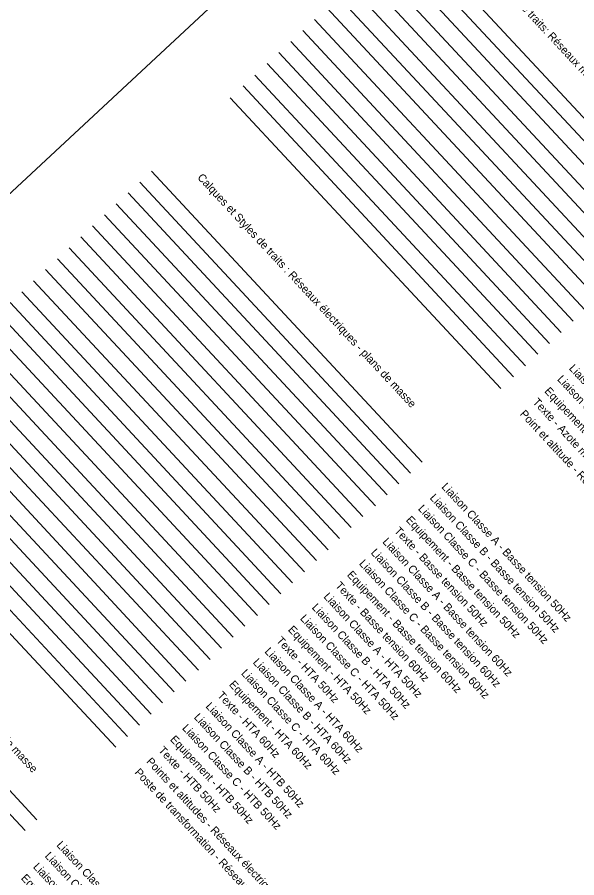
# Model space of a CAD drawing. Extents: x 704383 to 706615, y 7057567 to 7059313.
# Drawn here: x 706440.3 to 706475.2, y 7057729.7 to 7057783.5 of the extents above; entities that cross this region are included whole.
import ezdxf

# ---------------------------------------------------------------- set-up
doc = ezdxf.new("R2010")
doc.units = 0
for name, color, linetype in [('DH_CADRE -CARTOUCHE', 7, 'Continuous'), ('R_ELEC_ALT_POINT', 7, 'Continuous'), ('R_ELEC_BT_50HZ_EQUIP', 7, 'Continuous'), ('R_ELEC_BT_50HZ_LIAISON_CL_A', 7, 'Continuous'), ('R_ELEC_BT_50HZ_LIAISON_CL_B', 7, 'Continuous'), ('R_ELEC_BT_50HZ_LIAISON_CL_C', 7, 'Continuous'), ('R_ELEC_BT_50HZ_TEXTE', 7, 'Continuous'), ('R_ELEC_BT_60HZ_EQUIP', 7, 'Continuous'), ('R_ELEC_BT_60HZ_LIAISON_CL_A', 7, 'Continuous'), ('R_ELEC_BT_60HZ_LIAISON_CL_B', 7, 'Continuous'), ('R_ELEC_BT_60HZ_LIAISON_CL_C', 7, 'Continuous'), ('R_ELEC_BT_60HZ_TEXTE', 7, 'Continuous'), ('R_ELEC_HTA_50HZ_EQUIP', 7, 'Continuous'), ('R_ELEC_HTA_50HZ_LIAISON_CL_A', 7, 'Continuous'), ('R_ELEC_HTA_50HZ_LIAISON_CL_B', 7, 'Continuous'), ('R_ELEC_HTA_50HZ_LIAISON_CL_C', 7, 'Continuous'), ('R_ELEC_HTA_50HZ_TEXTE', 7, 'Continuous'), ('R_ELEC_HTA_60HZ_EQUIP', 7, 'Continuous'), ('R_ELEC_HTA_60HZ_LIAISON_CL_A', 7, 'Continuous'), ('R_ELEC_HTA_60HZ_LIAISON_CL_B', 7, 'Continuous'), ('R_ELEC_HTA_60HZ_LIAISON_CL_C', 7, 'Continuous'), ('R_ELEC_HTA_60HZ_TEXTE', 7, 'Continuous'), ('R_ELEC_HTB_50HZ_EQUIP', 7, 'Continuous'), ('R_ELEC_HTB_50HZ_LIAISON_CL_A', 7, 'Continuous'), ('R_ELEC_HTB_50HZ_LIAISON_CL_B', 7, 'Continuous'), ('R_ELEC_HTB_50HZ_LIAISON_CL_C', 7, 'Continuous'), ('R_ELEC_HTB_50HZ_TEXTE', 7, 'Continuous'), ('R_ELEC_IST_BT_50HZ_EQUIP', 7, 'Continuous'), ('R_ELEC_IST_BT_50HZ_LIAISON_CL_A', 7, 'Continuous'), ('R_ELEC_IST_BT_50HZ_LIAISON_CL_B', 7, 'Continuous'), ('R_ELEC_IST_BT_50HZ_LIAISON_CL_C', 7, 'Continuous'), ('R_ELEC_POSTE', 7, 'Continuous'), ('R_MED_ALT_POINT', 7, 'Continuous'), ('R_MED_AZOTE_CANALISATION_CL_A', 7, 'Continuous'), ('R_MED_AZOTE_CANALISATION_CL_B', 7, 'Continuous'), ('R_MED_AZOTE_CANALISATION_CL_C', 7, 'Continuous'), ('R_MED_AZOTE_EQUIP', 7, 'Continuous'), ('R_MED_AZOTE_TEXTE', 7, 'Continuous'), ('R_MED_OXYGENE_CANALISATION_CL_A', 7, 'Continuous'), ('R_MED_OXYGENE_CANALISATION_CL_B', 7, 'Continuous'), ('R_MED_OXYGENE_CANALISATION_CL_C', 7, 'Continuous'), ('R_MED_OXYGENE_EQUIP', 7, 'Continuous'), ('R_MED_OXYGENE_TEXTE', 7, 'Continuous'), ('R_MED_VIDE_CANALISATION_CL_A', 7, 'Continuous'), ('R_MED_VIDE_CANALISATION_CL_B', 7, 'Continuous'), ('R_MED_VIDE_CANALISATION_CL_C', 7, 'Continuous'), ('R_MED_VIDE_EQUIP', 7, 'Continuous'), ('R_MED_VIDE_TEXTE', 7, 'Continuous')]:
    doc.layers.add(name, color=color, linetype=linetype)

msp = doc.modelspace()

# ---------------------------------------------------------------- linework, layer by layer
at = {"layer": 'DH_CADRE -CARTOUCHE'}
msp.add_lwpolyline([(706481.837, 7057811.547), (706566.98, 7057720.028), (706402.247, 7057566.771), (706317.104, 7057658.289)], close=True, dxfattribs=at)
at = {"layer": 'R_ELEC_ALT_POINT'}
msp.add_line((706430.26, 7057756.734), (706447.172, 7057738.555), dxfattribs=at)
at = {"layer": 'R_ELEC_BT_50HZ_EQUIP'}
msp.add_line((706446.481, 7057771.824), (706463.393, 7057753.645), dxfattribs=at)
at = {"layer": 'R_ELEC_BT_50HZ_LIAISON_CL_A'}
msp.add_line((706448.677, 7057773.868), (706465.59, 7057755.689), dxfattribs=at)
at = {"layer": 'R_ELEC_BT_50HZ_LIAISON_CL_B'}
msp.add_line((706447.945, 7057773.187), (706464.857, 7057755.008), dxfattribs=at)
at = {"layer": 'R_ELEC_BT_50HZ_LIAISON_CL_C'}
msp.add_line((706447.213, 7057772.505), (706464.125, 7057754.327), dxfattribs=at)
at = {"layer": 'R_ELEC_BT_50HZ_TEXTE'}
msp.add_line((706445.748, 7057771.143), (706462.661, 7057752.964), dxfattribs=at)
at = {"layer": 'R_ELEC_BT_60HZ_EQUIP'}
msp.add_line((706442.797, 7057768.397), (706459.71, 7057750.219), dxfattribs=at)
at = {"layer": 'R_ELEC_BT_60HZ_LIAISON_CL_A'}
msp.add_line((706444.994, 7057770.441), (706461.881, 7057752.289), dxfattribs=at)
at = {"layer": 'R_ELEC_BT_60HZ_LIAISON_CL_B'}
msp.add_line((706444.261, 7057769.76), (706461.149, 7057751.608), dxfattribs=at)
at = {"layer": 'R_ELEC_BT_60HZ_LIAISON_CL_C'}
msp.add_line((706443.529, 7057769.079), (706460.417, 7057750.927), dxfattribs=at)
at = {"layer": 'R_ELEC_BT_60HZ_TEXTE'}
msp.add_line((706442.065, 7057767.716), (706458.977, 7057749.537), dxfattribs=at)
at = {"layer": 'R_ELEC_HTA_50HZ_EQUIP'}
msp.add_line((706439.114, 7057764.971), (706456.026, 7057746.792), dxfattribs=at)
at = {"layer": 'R_ELEC_HTA_50HZ_LIAISON_CL_A'}
msp.add_line((706441.31, 7057767.014), (706458.228, 7057748.829), dxfattribs=at)
at = {"layer": 'R_ELEC_HTA_50HZ_LIAISON_CL_B'}
msp.add_line((706440.578, 7057766.333), (706457.496, 7057748.148), dxfattribs=at)
at = {"layer": 'R_ELEC_HTA_50HZ_LIAISON_CL_C'}
msp.add_line((706439.846, 7057765.652), (706456.764, 7057747.467), dxfattribs=at)
at = {"layer": 'R_ELEC_HTA_50HZ_TEXTE'}
msp.add_line((706438.382, 7057764.29), (706455.294, 7057746.111), dxfattribs=at)
at = {"layer": 'R_ELEC_HTA_60HZ_EQUIP'}
msp.add_line((706435.43, 7057761.544), (706452.343, 7057743.365), dxfattribs=at)
at = {"layer": 'R_ELEC_HTA_60HZ_LIAISON_CL_A'}
msp.add_line((706437.627, 7057763.587), (706454.514, 7057745.435), dxfattribs=at)
at = {"layer": 'R_ELEC_HTA_60HZ_LIAISON_CL_B'}
msp.add_line((706436.895, 7057762.906), (706453.782, 7057744.754), dxfattribs=at)
at = {"layer": 'R_ELEC_HTA_60HZ_LIAISON_CL_C'}
msp.add_line((706436.162, 7057762.225), (706453.05, 7057744.073), dxfattribs=at)
at = {"layer": 'R_ELEC_HTA_60HZ_TEXTE'}
msp.add_line((706434.698, 7057760.863), (706451.611, 7057742.684), dxfattribs=at)
at = {"layer": 'R_ELEC_HTB_50HZ_EQUIP'}
msp.add_line((706431.747, 7057758.117), (706448.659, 7057739.938), dxfattribs=at)
at = {"layer": 'R_ELEC_HTB_50HZ_LIAISON_CL_A'}
msp.add_line((706433.946, 7057760.163), (706450.833, 7057742.011), dxfattribs=at)
at = {"layer": 'R_ELEC_HTB_50HZ_LIAISON_CL_B'}
msp.add_line((706433.214, 7057759.482), (706450.101, 7057741.33), dxfattribs=at)
at = {"layer": 'R_ELEC_HTB_50HZ_LIAISON_CL_C'}
msp.add_line((706432.482, 7057758.801), (706449.369, 7057740.649), dxfattribs=at)
at = {"layer": 'R_ELEC_HTB_50HZ_TEXTE'}
msp.add_line((706431.015, 7057757.436), (706447.927, 7057739.257), dxfattribs=at)
at = {"layer": 'R_ELEC_IST_BT_50HZ_LIAISON_CL_A'}
msp.add_line((706424.63, 7057751.496), (706441.512, 7057733.349), dxfattribs=at)
at = {"layer": 'R_ELEC_IST_BT_50HZ_LIAISON_CL_B'}
msp.add_line((706423.898, 7057750.814), (706440.78, 7057732.668), dxfattribs=at)
at = {"layer": 'R_ELEC_POSTE'}
msp.add_line((706429.528, 7057756.052), (706446.44, 7057737.874), dxfattribs=at)
at = {"layer": 'R_MED_ALT_POINT'}
msp.add_line((706470.5, 7057760.278), (706453.598, 7057778.446), dxfattribs=at)
at = {"layer": 'R_MED_AZOTE_CANALISATION_CL_A'}
msp.add_line((706457.372, 7057781.957), (706474.274, 7057763.789), dxfattribs=at)
at = {"layer": 'R_MED_AZOTE_CANALISATION_CL_B'}
msp.add_line((706456.64, 7057781.276), (706473.542, 7057763.108), dxfattribs=at)
at = {"layer": 'R_MED_AZOTE_CANALISATION_CL_C'}
msp.add_line((706455.908, 7057780.595), (706472.81, 7057762.427), dxfattribs=at)
at = {"layer": 'R_MED_AZOTE_EQUIP'}
msp.add_line((706472.033, 7057761.703), (706455.13, 7057779.871), dxfattribs=at)
at = {"layer": 'R_MED_AZOTE_TEXTE'}
msp.add_line((706471.3, 7057761.022), (706454.398, 7057779.19), dxfattribs=at)
at = {"layer": 'R_MED_OXYGENE_CANALISATION_CL_A'}
msp.add_line((706464.807, 7057788.874), (706481.709, 7057770.706), dxfattribs=at)
at = {"layer": 'R_MED_OXYGENE_CANALISATION_CL_B'}
msp.add_line((706464.098, 7057788.214), (706481, 7057770.046), dxfattribs=at)
at = {"layer": 'R_MED_OXYGENE_CANALISATION_CL_C'}
msp.add_line((706463.365, 7057787.533), (706480.268, 7057769.365), dxfattribs=at)
at = {"layer": 'R_MED_OXYGENE_EQUIP'}
msp.add_line((706479.49, 7057768.641), (706462.588, 7057786.81), dxfattribs=at)
at = {"layer": 'R_MED_OXYGENE_TEXTE'}
msp.add_line((706478.758, 7057767.96), (706461.856, 7057786.128), dxfattribs=at)
at = {"layer": 'R_MED_VIDE_CANALISATION_CL_A'}
msp.add_line((706461.101, 7057785.426), (706477.993, 7057767.269), dxfattribs=at)
at = {"layer": 'R_MED_VIDE_CANALISATION_CL_B'}
msp.add_line((706460.369, 7057784.745), (706477.261, 7057766.588), dxfattribs=at)
at = {"layer": 'R_MED_VIDE_CANALISATION_CL_C'}
msp.add_line((706459.637, 7057784.064), (706476.529, 7057765.907), dxfattribs=at)
at = {"layer": 'R_MED_VIDE_EQUIP'}
msp.add_line((706475.761, 7057765.172), (706458.859, 7057783.34), dxfattribs=at)
at = {"layer": 'R_MED_VIDE_TEXTE'}
msp.add_line((706475.029, 7057764.491), (706458.127, 7057782.659), dxfattribs=at)

# ---------------------------------------------------------------- texts
at = {"layer": 'DH_CADRE -CARTOUCHE'}
for s, p in [(' Calques et Styles de traits: Réseaux médicaux - plans de masse', (706467.712, 7057788.366)), (' Calques et Styles de traits : Réseaux électriques - plans de masse', (706451.384, 7057773.573)), (' Calques et Styles de traits : Réseaux électriques IST - plans de masse', (706426.9, 7057751.67))]:
    msp.add_text(s, height=0.5, rotation=312.9332, dxfattribs=at).set_placement(p)
at = {"layer": 'R_ELEC_ALT_POINT'}
msp.add_text('Points et altitudes - Réseaux électriques', height=0.5, rotation=312.9332, dxfattribs=at).set_placement((706448.32, 7057736.954))
at = {"layer": 'R_ELEC_BT_50HZ_EQUIP'}
msp.add_text('Equipement - Basse tension 50Hz', height=0.5, rotation=312.9332, dxfattribs=at).set_placement((706464.541, 7057752.045))
at = {"layer": 'R_ELEC_BT_50HZ_LIAISON_CL_A'}
msp.add_text('Liaison Classe A - Basse tension 50Hz', height=0.5, rotation=312.9332, dxfattribs=at).set_placement((706466.76, 7057754.11))
at = {"layer": 'R_ELEC_BT_50HZ_LIAISON_CL_B'}
msp.add_text('Liaison Classe B - Basse tension 50Hz', height=0.5, rotation=312.9332, dxfattribs=at).set_placement((706466.028, 7057753.428))
at = {"layer": 'R_ELEC_BT_50HZ_LIAISON_CL_C'}
msp.add_text('Liaison Classe C - Basse tension 50Hz', height=0.5, rotation=312.9332, dxfattribs=at).set_placement((706465.295, 7057752.747))
at = {"layer": 'R_ELEC_BT_50HZ_TEXTE'}
msp.add_text('Texte - Basse tension 50Hz', height=0.5, rotation=312.9332, dxfattribs=at).set_placement((706463.808, 7057751.364))
at = {"layer": 'R_ELEC_BT_60HZ_EQUIP'}
msp.add_text('Equipement - Basse tension 60Hz', height=0.5, rotation=312.9332, dxfattribs=at).set_placement((706460.857, 7057748.618))
at = {"layer": 'R_ELEC_BT_60HZ_LIAISON_CL_A'}
msp.add_text('Liaison Classe A - Basse tension 60Hz', height=0.5, rotation=312.9332, dxfattribs=at).set_placement((706463.076, 7057750.683))
at = {"layer": 'R_ELEC_BT_60HZ_LIAISON_CL_B'}
msp.add_text('Liaison Classe B - Basse tension 60Hz', height=0.5, rotation=312.9332, dxfattribs=at).set_placement((706462.344, 7057750.002))
at = {"layer": 'R_ELEC_BT_60HZ_LIAISON_CL_C'}
msp.add_text('Liaison Classe C - Basse tension 60Hz', height=0.5, rotation=312.9332, dxfattribs=at).set_placement((706461.612, 7057749.32))
at = {"layer": 'R_ELEC_BT_60HZ_TEXTE'}
msp.add_text('Texte - Basse tension 60Hz', height=0.5, rotation=312.9332, dxfattribs=at).set_placement((706460.125, 7057747.937))
at = {"layer": 'R_ELEC_HTA_50HZ_EQUIP'}
msp.add_text('Equipement - HTA 50Hz', height=0.5, rotation=312.9332, dxfattribs=at).set_placement((706457.174, 7057745.191))
at = {"layer": 'R_ELEC_HTA_50HZ_LIAISON_CL_A'}
msp.add_text('Liaison Classe A - HTA 50Hz', height=0.5, rotation=312.9332, dxfattribs=at).set_placement((706459.393, 7057747.256))
at = {"layer": 'R_ELEC_HTA_50HZ_LIAISON_CL_B'}
msp.add_text('Liaison Classe B - HTA 50Hz', height=0.5, rotation=312.9332, dxfattribs=at).set_placement((706458.661, 7057746.575))
at = {"layer": 'R_ELEC_HTA_50HZ_LIAISON_CL_C'}
msp.add_text('Liaison Classe C - HTA 50Hz', height=0.5, rotation=312.9332, dxfattribs=at).set_placement((706457.929, 7057745.894))
at = {"layer": 'R_ELEC_HTA_50HZ_TEXTE'}
msp.add_text('Texte - HTA 50Hz', height=0.5, rotation=312.9332, dxfattribs=at).set_placement((706456.442, 7057744.51))
at = {"layer": 'R_ELEC_HTA_60HZ_EQUIP'}
msp.add_text('Equipement - HTA 60Hz', height=0.5, rotation=312.9332, dxfattribs=at).set_placement((706453.49, 7057741.764))
at = {"layer": 'R_ELEC_HTA_60HZ_LIAISON_CL_A'}
msp.add_text('Liaison Classe A - HTA 60Hz', height=0.5, rotation=312.9332, dxfattribs=at).set_placement((706455.709, 7057743.829))
at = {"layer": 'R_ELEC_HTA_60HZ_LIAISON_CL_B'}
msp.add_text('Liaison Classe B - HTA 60Hz', height=0.5, rotation=312.9332, dxfattribs=at).set_placement((706454.977, 7057743.148))
at = {"layer": 'R_ELEC_HTA_60HZ_LIAISON_CL_C'}
msp.add_text('Liaison Classe C - HTA 60Hz', height=0.5, rotation=312.9332, dxfattribs=at).set_placement((706454.245, 7057742.467))
at = {"layer": 'R_ELEC_HTA_60HZ_TEXTE'}
msp.add_text('Texte - HTA 60Hz', height=0.5, rotation=312.9332, dxfattribs=at).set_placement((706452.758, 7057741.083))
at = {"layer": 'R_ELEC_HTB_50HZ_EQUIP'}
msp.add_text('Equipement - HTB 50Hz', height=0.5, rotation=312.9332, dxfattribs=at).set_placement((706449.807, 7057738.338))
at = {"layer": 'R_ELEC_HTB_50HZ_LIAISON_CL_A'}
msp.add_text('Liaison Classe A - HTB 50Hz', height=0.5, rotation=312.9332, dxfattribs=at).set_placement((706452.026, 7057740.402))
at = {"layer": 'R_ELEC_HTB_50HZ_LIAISON_CL_B'}
msp.add_text('Liaison Classe B - HTB 50Hz', height=0.5, rotation=312.9332, dxfattribs=at).set_placement((706451.294, 7057739.721))
at = {"layer": 'R_ELEC_HTB_50HZ_LIAISON_CL_C'}
msp.add_text('Liaison Classe C - HTB 50Hz', height=0.5, rotation=312.9332, dxfattribs=at).set_placement((706450.562, 7057739.04))
at = {"layer": 'R_ELEC_HTB_50HZ_TEXTE'}
msp.add_text('Texte - HTB 50Hz', height=0.5, rotation=312.9332, dxfattribs=at).set_placement((706449.075, 7057737.656))
at = {"layer": 'R_ELEC_IST_BT_50HZ_EQUIP'}
msp.add_text('Equipement - IST Basse tension 50Hz', height=0.5, rotation=312.9332, dxfattribs=at).set_placement((706440.493, 7057729.673))
at = {"layer": 'R_ELEC_IST_BT_50HZ_LIAISON_CL_A'}
msp.add_text('Liaison Classe A - IST Basse tension 50Hz', height=0.5, rotation=312.9332, dxfattribs=at).set_placement((706442.712, 7057731.737))
at = {"layer": 'R_ELEC_IST_BT_50HZ_LIAISON_CL_B'}
msp.add_text('Liaison Classe B - IST Basse tension 50Hz', height=0.5, rotation=312.9332, dxfattribs=at).set_placement((706441.98, 7057731.056))
at = {"layer": 'R_ELEC_IST_BT_50HZ_LIAISON_CL_C'}
msp.add_text('Liaison Classe C - IST Basse tension 50Hz', height=0.5, rotation=312.9332, dxfattribs=at).set_placement((706441.248, 7057730.375))
at = {"layer": 'R_ELEC_POSTE'}
msp.add_text('Poste de transformation - Réseaux électriques', height=0.5, rotation=312.9332, dxfattribs=at).set_placement((706447.588, 7057736.273))
at = {"layer": 'R_MED_ALT_POINT'}
msp.add_text('Point et altitude - Réseaux médicaux', height=0.5, rotation=312.9332, dxfattribs=at).set_placement((706471.658, 7057758.666))
at = {"layer": 'R_MED_AZOTE_CANALISATION_CL_B'}
msp.add_text('Liaison Classe B - Azote médical', height=0.5, rotation=312.9332, dxfattribs=at).set_placement((706474.723, 7057761.518))
at = {"layer": 'R_MED_AZOTE_CANALISATION_CL_C'}
msp.add_text('Liaison Classe C - Azote médical', height=0.5, rotation=312.9332, dxfattribs=at).set_placement((706473.99, 7057760.837))
at = {"layer": 'R_MED_AZOTE_EQUIP'}
msp.add_text('Equipement - Azote médical', height=0.5, rotation=312.9332, dxfattribs=at).set_placement((706473.19, 7057760.092))
at = {"layer": 'R_MED_AZOTE_TEXTE'}
msp.add_text('Texte - Azote médical', height=0.5, rotation=312.9332, dxfattribs=at).set_placement((706472.458, 7057759.411))

doc.saveas('drawing.dxf')
